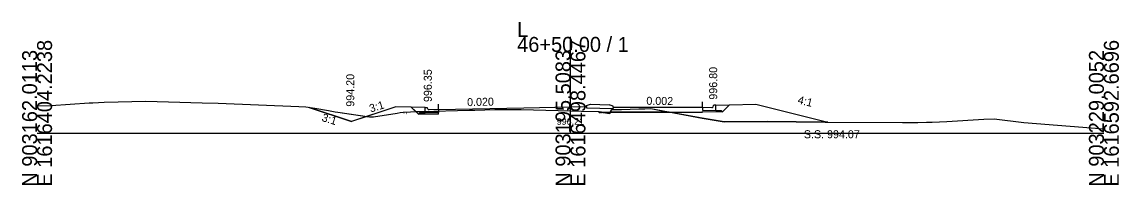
# Model space of a CAD drawing. Extents: x 1009 to 7438, y -1586 to 7964.
# Drawn here: x 4032.1 to 4237.7, y 4414 to 4444.6 of the extents above; entities that cross this region are included whole.
import ezdxf

# ---------------------------------------------------------------- set-up
doc = ezdxf.new("R2010")
doc.units = 0
for name, color, linetype in [('Exist Cross Section Cell', 7, 'Continuous'), ('Exist XS Center Line Elevation Label', 7, 'Continuous'), ('Exist XS Ground Line', 7, 'Continuous'), ('Prop XS Dump Level', 7, 'Continuous'), ('Prop XS Earthwork Shape', 7, 'Continuous'), ('Prop XS EOT Tick Mark', 7, 'Continuous'), ('Prop XS Finish Grade', 7, 'Continuous'), ('Prop XS Finish Grade CurbGutter', 7, 'Continuous'), ('Prop XS Finish Grade Earthwork', 7, 'Continuous'), ('Prop XS Finish Grade Pavement', 7, 'Continuous'), ('Prop XS Hydro Elevations', 7, 'Continuous'), ('Prop XS Pvmt Edge Slope', 7, 'Continuous'), ('Prop XS SE Text', 7, 'Continuous'), ('Prop XS Side Slope Text', 7, 'Continuous'), ('Prop XS SS Elevation Text', 7, 'Continuous'), ('Prop XS Subgrade CurbGutter', 7, 'Continuous'), ('Prop XS Subgrade Earthwork', 7, 'Continuous')]:
    doc.layers.add(name, color=color, linetype=linetype)

msp = doc.modelspace()

# ---------------------------------------------------------------- linework, layer by layer
at = {"layer": 'Exist Cross Section Cell'}
for p, q in [((4134.89, 4423.73), (4134.89, 4441.77)), ((4034.89, 4423.73), (4134.89, 4423.73)), ((4134.89, 4423.73), (4234.89, 4423.73))]:
    msp.add_line(p, q, dxfattribs=at)
at = {"layer": 'Exist XS Ground Line'}
for p, q in [((4034.89, 4428.85), (4037.54, 4428.93)), ((4037.54, 4428.93), (4044.63, 4429.42)), ((4044.63, 4429.42), (4045.37, 4429.46)), ((4045.37, 4429.46), (4047.45, 4429.53)), ((4047.45, 4429.53), (4055.25, 4429.74)), ((4055.25, 4429.74), (4059.55, 4429.62)), ((4059.55, 4429.62), (4065.86, 4429.41)), ((4065.86, 4429.41), (4068.86, 4429.37)), ((4068.86, 4429.37), (4083.94, 4428.73)), ((4083.94, 4428.73), (4085.26, 4428.68)), ((4085.26, 4428.68), (4086.97, 4428.41)), ((4086.97, 4428.41), (4089.55, 4427.98)), ((4147.7, 4428.28), (4148.83, 4428.32)), ((4148.83, 4428.32), (4149.98, 4428.34)), ((4149.98, 4428.34), (4159.59, 4426.54)), ((4089.55, 4427.98), (4090.79, 4427.73)), ((4090.79, 4427.73), (4091.25, 4427.67)), ((4091.25, 4427.67), (4097.19, 4426.8)), ((4097.19, 4426.8), (4097.94, 4426.8)), ((4097.94, 4426.8), (4102.38, 4427.5)), ((4102.38, 4427.5), (4102.97, 4427.59)), ((4102.97, 4427.59), (4103.52, 4427.68)), ((4103.52, 4427.68), (4104.89, 4427.76)), ((4104.89, 4427.76), (4106.99, 4427.82)), ((4106.99, 4427.82), (4115.97, 4428.05)), ((4115.97, 4428.05), (4116.98, 4428.08)), ((4116.98, 4428.08), (4120.7, 4428.2)), ((4120.7, 4428.2), (4124.69, 4428.18)), ((4124.69, 4428.18), (4125.66, 4428.18)), ((4125.66, 4428.18), (4134.89, 4427.93)), ((4134.89, 4427.93), (4136.95, 4427.88)), ((4136.95, 4427.88), (4140.2, 4427.79)), ((4140.2, 4427.79), (4140.33, 4427.77)), ((4140.33, 4427.77), (4140.67, 4427.71)), ((4140.67, 4427.71), (4142.19, 4427.45)), ((4142.19, 4427.45), (4142.65, 4428.15)), ((4142.65, 4428.15), (4144.46, 4428.2)), ((4144.46, 4428.2), (4147.7, 4428.28)), ((4159.59, 4426.54), (4163.67, 4425.86)), ((4205.47, 4425.96), (4212.38, 4426.36)), ((4212.38, 4426.36), (4214.34, 4426.46)), ((4214.34, 4426.46), (4219.85, 4425.72)), ((4163.67, 4425.86), (4171.77, 4425.91)), ((4171.77, 4425.91), (4182.61, 4425.81)), ((4182.61, 4425.81), (4197.15, 4425.77)), ((4197.15, 4425.77), (4200.01, 4425.75)), ((4200.01, 4425.75), (4201.62, 4425.78)), ((4201.62, 4425.78), (4202.72, 4425.81)), ((4202.72, 4425.81), (4205.47, 4425.96)), ((4219.85, 4425.72), (4234.89, 4424.58))]:
    msp.add_line(p, q, dxfattribs=at)
at = {"layer": 'Prop XS Dump Level'}
for p, q in [((4110.14, 4428.2), (4126.14, 4428.52)), ((4110.14, 4428.2), (4126.14, 4428.52)), ((4126.14, 4428.52), (4134.89, 4428.69)), ((4126.14, 4428.52), (4134.89, 4428.69)), ((4143.64, 4428.62), (4159.64, 4428.62)), ((4143.64, 4428.62), (4159.64, 4428.62))]:
    msp.add_line(p, q, dxfattribs=at)
at = {"layer": 'Prop XS Earthwork Shape'}
for points in [[(4089.55, 4427.98), (4090.79, 4427.73), (4091.25, 4427.67), (4096.68, 4426.88), (4093.85, 4425.93), (4085.89, 4428.58), (4086.97, 4428.41)], [(4096.68, 4426.88), (4097.19, 4426.8), (4097.94, 4426.8), (4102.38, 4427.5), (4102.97, 4427.59), (4103.52, 4427.68), (4104.89, 4427.76), (4105.9, 4427.79), (4105.05, 4428.63), (4102.14, 4428.7)], [(4148.83, 4428.32), (4149.98, 4428.34), (4153.37, 4427.7), (4142.36, 4427.7), (4142.65, 4428.15), (4144.46, 4428.2), (4147.7, 4428.28)], [(4153.37, 4427.7), (4159.65, 4427.7), (4159.64, 4427.79), (4163.39, 4427.76), (4164.71, 4429.08), (4169.64, 4429.18), (4183.14, 4425.81), (4182.61, 4425.81), (4171.77, 4425.91), (4163.67, 4425.86), (4159.59, 4426.54)], [(4105.9, 4427.79), (4106.99, 4427.82), (4107.64, 4427.83), (4107.64, 4427.57), (4106.64, 4427.55), (4106.39, 4427.29)], [(4107.64, 4427.57), (4106.64, 4427.55), (4106.39, 4427.29), (4110.14, 4427.37), (4110.14, 4427.62)], [(4110.14, 4427.9), (4110.14, 4427.62), (4107.64, 4427.57), (4107.64, 4427.83)], [(4140.33, 4427.77), (4140.67, 4427.71), (4140.7, 4427.7), (4140.2, 4427.7), (4140.2, 4427.79)], [(4140.7, 4427.7), (4142.36, 4427.7), (4142.19, 4427.45)]]:
    msp.add_lwpolyline(points, close=True, dxfattribs=at)
at = {"layer": 'Prop XS EOT Tick Mark'}
for p, q in [((4110.14, 4428.2), (4110.14, 4429.2)), ((4159.64, 4428.62), (4159.64, 4429.62))]:
    msp.add_line(p, q, dxfattribs=at)
at = {"layer": 'Prop XS Finish Grade'}
for p, q in [((4107.64, 4428.58), (4105.05, 4428.63)), ((4162.14, 4429.02), (4164.71, 4429.08))]:
    msp.add_line(p, q, dxfattribs=at)
at = {"layer": 'Prop XS Finish Grade CurbGutter'}
for p, q in [((4107.64, 4428.58), (4107.89, 4428.58)), ((4107.89, 4428.58), (4108.02, 4428.55)), ((4108.11, 4428.46), (4108.02, 4428.55)), ((4108.18, 4428.21), (4108.11, 4428.46)), ((4137.89, 4428.92), (4138.64, 4429.17)), ((4137.89, 4428.75), (4137.89, 4428.92)), ((4138.64, 4429.17), (4142.14, 4429.04)), ((4142.89, 4428.79), (4142.14, 4429.04)), ((4142.89, 4428.62), (4142.89, 4428.79)), ((4159.64, 4428.62), (4161.39, 4428.53)), ((4161.39, 4428.53), (4161.52, 4428.56)), ((4161.52, 4428.56), (4161.61, 4428.65)), ((4161.61, 4428.65), (4161.68, 4428.9)), ((4161.68, 4428.9), (4161.77, 4428.99)), ((4161.89, 4429.02), (4161.77, 4428.99)), ((4162.14, 4429.02), (4161.89, 4429.02)), ((4108.27, 4428.12), (4108.18, 4428.21)), ((4108.39, 4428.09), (4108.27, 4428.12)), ((4110.14, 4428.2), (4108.39, 4428.09))]:
    msp.add_line(p, q, dxfattribs=at)
at = {"layer": 'Prop XS Finish Grade Earthwork'}
for p, q in [((4085.89, 4428.58), (4093.85, 4425.93)), ((4102.14, 4428.7), (4093.85, 4425.93)), ((4105.05, 4428.63), (4102.14, 4428.7)), ((4164.71, 4429.08), (4169.64, 4429.18)), ((4169.64, 4429.18), (4183.14, 4425.81))]:
    msp.add_line(p, q, dxfattribs=at)
at = {"layer": 'Prop XS Finish Grade Pavement'}
for p, q in [((4110.14, 4428.2), (4126.14, 4428.52)), ((4126.14, 4428.52), (4137.89, 4428.75)), ((4142.89, 4428.62), (4159.64, 4428.62))]:
    msp.add_line(p, q, dxfattribs=at)
at = {"layer": 'Prop XS Pvmt Edge Slope'}
for p, q in [((4106.64, 4427.55), (4106.39, 4427.29)), ((4107.64, 4427.57), (4106.64, 4427.55)), ((4162.14, 4428.02), (4163.14, 4428.01)), ((4163.14, 4428.01), (4163.39, 4427.76))]:
    msp.add_line(p, q, dxfattribs=at)
at = {"layer": 'Prop XS Subgrade CurbGutter'}
for p, q in [((4107.64, 4427.57), (4107.64, 4428.58)), ((4137.89, 4428.75), (4137.89, 4428.5)), ((4137.89, 4428.5), (4142.89, 4428.37)), ((4142.89, 4428.62), (4142.89, 4428.37)), ((4159.64, 4428.62), (4159.64, 4428.04)), ((4162.14, 4428.02), (4162.14, 4429.02)), ((4110.14, 4427.62), (4107.64, 4427.57)), ((4110.14, 4428.2), (4110.14, 4427.62)), ((4159.64, 4428.04), (4162.14, 4428.02))]:
    msp.add_line(p, q, dxfattribs=at)
at = {"layer": 'Prop XS Subgrade Earthwork'}
for p, q in [((4106.39, 4427.29), (4105.05, 4428.63)), ((4163.39, 4427.76), (4164.71, 4429.08)), ((4110.14, 4427.37), (4106.39, 4427.29)), ((4110.14, 4427.28), (4110.14, 4427.9)), ((4110.14, 4427.28), (4110.14, 4427.37)), ((4140.2, 4427.79), (4140.2, 4427.7)), ((4140.2, 4427.7), (4159.65, 4427.7)), ((4159.64, 4427.7), (4159.64, 4427.79)), ((4159.64, 4427.79), (4163.39, 4427.76))]:
    msp.add_line(p, q, dxfattribs=at)

# ---------------------------------------------------------------- texts
at = {"layer": 'Exist Cross Section Cell'}
for s, p in [('L', (4124.89, 4441.77)), ('46+50.00 / 1', (4124.89, 4438.97))]:
    msp.add_text(s, height=2.8, dxfattribs=at).set_placement(p)
for s, p in [('E 1616404.2238', (4037.69, 4413.73)), ('E 1616498.4467', (4137.69, 4413.73)), ('E 1616592.6696', (4237.69, 4413.73)), ('N 903162.0113', (4034.89, 4413.73)), ('N 903195.5083', (4134.89, 4413.73)), ('N 903229.0052', (4234.89, 4413.73))]:
    msp.add_text(s, height=2.8, rotation=90, dxfattribs=at).set_placement(p)
at = {"layer": 'Exist XS Center Line Elevation Label'}
msp.add_text('996.21', height=1.25, dxfattribs=at).set_placement((4132.31, 4425.31))
at = {"layer": 'Prop XS Dump Level'}
for p in [(4103.52, 4427.38), (4140.2, 4427.49), (4140.2, 4427.49), (4140.2, 4427.49)]:
    msp.add_text('Eop', height=0.3, dxfattribs=at).set_placement(p)
at = {"layer": 'Prop XS Hydro Elevations'}
for s, p in [('994.20', (4094.35, 4428.71)), ('996.35', (4108.89, 4429.58)), ('996.80', (4162.39, 4430.02))]:
    msp.add_text(s, height=1.5, rotation=90, dxfattribs=at).set_placement(p)
at = {"layer": 'Prop XS SE Text'}
for s, rotation, p in [('0.020', 1.1458, (4115.52, 4428.81)), ('0.002', 359.4666, (4149.11, 4429.06))]:
    msp.add_text(s, height=1.5, rotation=rotation, dxfattribs=at).set_placement(p)
at = {"layer": 'Prop XS Side Slope Text'}
for s, rotation, p in [('4:1', 345.9638, (4177.38, 4429.33)), ('3:1', 16.9342, (4097.44, 4427.61)), ('3:1', 343.0658, (4088.15, 4426.05))]:
    msp.add_text(s, height=1.5, rotation=rotation, dxfattribs=at).set_placement(p)
at = {"layer": 'Prop XS SS Elevation Text'}
msp.add_text('S.S. 994.07', height=1.5, dxfattribs=at).set_placement((4178.64, 4422.8))

doc.saveas('drawing.dxf')
